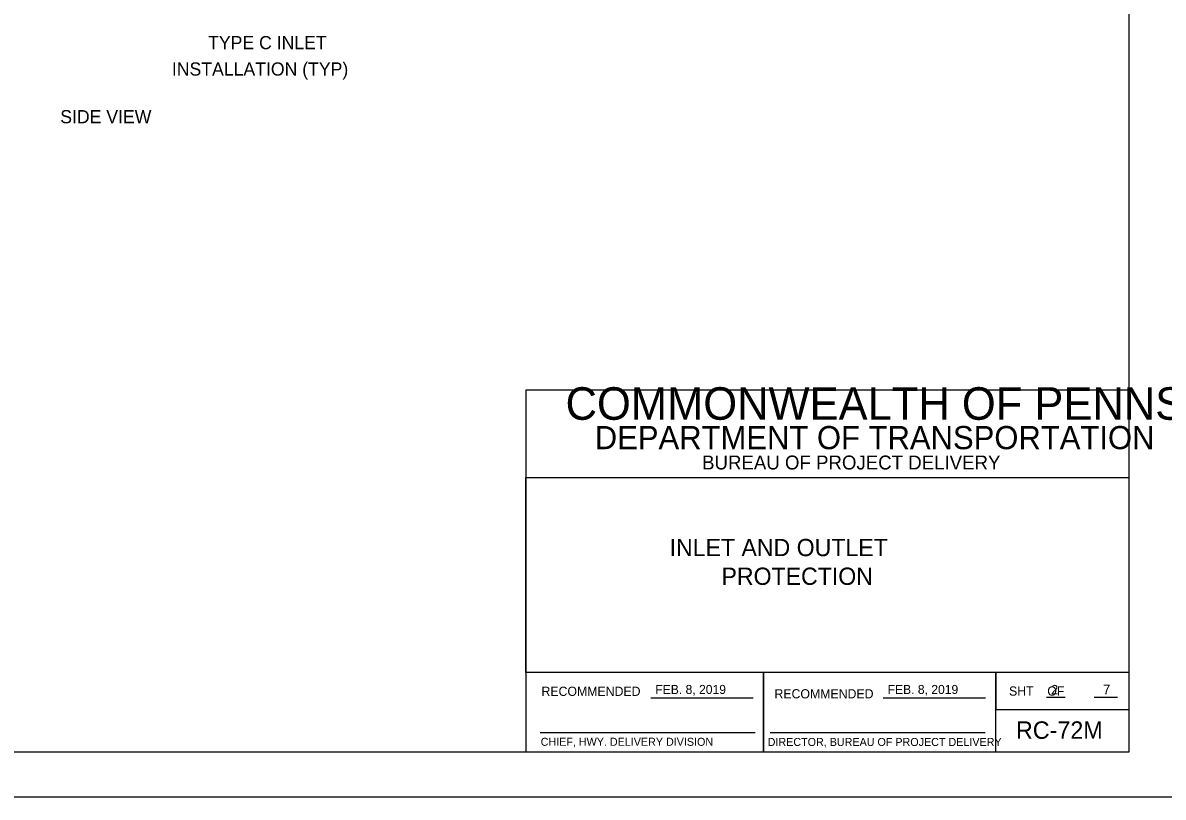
# Model space of a CAD drawing. Extents: x 636183 to 639890, y 299162 to 300538.
# Drawn here: x 636921.1 to 637299.2, y 299350.4 to 299607.2 of the extents above; entities that cross this region are included whole.
import ezdxf

# ---------------------------------------------------------------- set-up
doc = ezdxf.new("R2010")
doc.units = 0
for name, color, linetype in [('1', 7, 'Continuous'), ('Default', 7, 'Continuous'), ('PLT-BNDY', 7, 'Continuous')]:
    doc.layers.add(name, color=color, linetype=linetype)

msp = doc.modelspace()

# ---------------------------------------------------------------- linework, layer by layer
at = {"layer": '1'}
for p, q in [((637129.38, 299383.44), (637163.27, 299383.44)), ((637206.38, 299383.44), (637240.25, 299383.44)), ((637260.54, 299383.66), (637266.68, 299383.66)), ((637276.35, 299383.66), (637283.99, 299383.66)), ((637092.68, 299371.87), (637163.93, 299371.87)), ((637168.85, 299371.87), (637240.19, 299371.87))]:
    msp.add_line(p, q, dxfattribs=at)
msp.add_lwpolyline([(637287.91, 299365.45), (637287.91, 299929.45), (636501.91, 299929.45), (636501.91, 299365.45), (637287.91, 299365.45), (637287.91, 299391.81), (637087.91, 299391.81), (637087.91, 299456.49), (637287.91, 299456.49), (637287.91, 299485.45), (637087.91, 299485.45), (637087.91, 299365.45), (637166.72, 299365.45), (637166.72, 299391.81), (637166.72, 299365.45), (637243.72, 299365.45), (637243.72, 299391.81), (637243.72, 299379.49), (637287.91, 299379.49)], dxfattribs=at)
at = {"layer": 'PLT-BNDY'}
msp.add_lwpolyline([(636461.91, 299944.45), (637302.91, 299944.45), (637302.91, 299350.45), (636461.91, 299350.45)], close=True, dxfattribs=at)

# ---------------------------------------------------------------- texts
at = {"layer": '1'}
for s, height, p in [('COMMONWEALTH OF PENNSYLVANIA', 10.7834, (637101.07, 299475.59)), ('DEPARTMENT OF TRANSPORTATION', 7.6843, (637110.75, 299465.84)), ('BUREAU OF PROJECT DELIVERY', 4.6221, (637146.32, 299459.11)), ('RECOMMENDED', 3.048, (637093.08, 299384.04)), ('FEB. 8, 2019', 3, (637130.82, 299384.67)), ('FEB. 8, 2019', 3, (637207.82, 299384.67)), ('SHT    OF', 3.048, (637248.08, 299384.12)), ('2', 3.13, (637262.05, 299384.54)), ('7', 3.13, (637279.28, 299384.59)), ('APPROVED', 0.0192, (637130.94, 299383.38)), ('APPROVED', 0.0192, (637130.94, 299383.38)), ('APPROVED', 0.0192, (637130.94, 299383.38)), ('APPROVED', 0.0192, (637130.94, 299383.38)), ('APPROVED', 0.0192, (637130.94, 299383.38)), ('APPROVED', 0.0192, (637130.94, 299383.38)), ('APPROVED', 0.0192, (637130.94, 299383.38)), ('APPROVED', 0.0192, (637130.94, 299383.38)), ('RECOMMENDED', 3.048, (637170.32, 299383.21)), ('CHIEF, HWY. DELIVERY DIVISION', 2.6623, (637092.82, 299367.49)), ('DIRECTOR, BUREAU OF PROJECT DELIVERY', 2.6623, (637168.07, 299367.43))]:
    msp.add_text(s, height=height, dxfattribs=at).set_placement(p)
at = {"layer": 'Default'}
for s, height, p in [('TYPE C INLET', 4.3721, (636982.57, 299598.46)), ('INSTALLATION (TYP)', 4.3721, (636970.56, 299589.71)), ('SIDE VIEW', 4.372, (636933.55, 299573.9)), ('INLET AND OUTLET', 5.7257, (637135.56, 299430.37)), ('PROTECTION', 5.726, (637152.76, 299420.85)), ('RC-72M', 5.779, (637250.37, 299369.81))]:
    msp.add_text(s, height=height, dxfattribs=at).set_placement(p)

doc.saveas('drawing.dxf')
